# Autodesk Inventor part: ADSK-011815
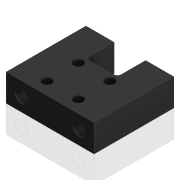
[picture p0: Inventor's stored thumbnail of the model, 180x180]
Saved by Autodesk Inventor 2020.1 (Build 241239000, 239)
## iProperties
Created: 1999-12
Part Number: ADSK-011815
Document SubType Name: Modeling
Designer: glanglot
Material: Générique
Density: 1 g/cm^3
Appearance: Rubber-Black
Mass: 572.86 g
Surface Area: 781.835 cm^2
Volume: 572.86 cm^3
Control State: 0
Master: False
Checked Out: False
Shininess: 0.0
Length Units: 11269
Angle Units: 11279
Time Units: 11290
Mass Units: 11283
Length Display Precision: 3
Angle Display Precision: 2
Compacted: True
Dimensions: 140x43x127 mm
Mass: 0,573 kg
Density: 0.0
Volumn: 0.0
Area: 0.0
PropertySet Name: Model Information
Author: glanglot
Revision Number: -
Title: ADSK-011815
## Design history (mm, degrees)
node "Solide1"
  node "Extrusion1" dims "d2" = 127, "d3" = 0
  node "Hole1" dims "d7" = 20, "d8" = 9.525, "d9" = 6.35, "d10" = 60 deg, "d11" = 19.05, "d12" = 118 deg, "d42" = 6
  node "Hole2" dims "d16" = 9, "d17" = 15, "d18" = 9, "d19" = 60 deg, "d20" = 19.05, "d21" = 118 deg, "d46" = 6
  node "Hole3" dims "d27" = 4.134, "d28" = 15.875, "d29" = 11.176, "d30" = 60 deg, "d31" = 14.2, "d32" = 118 deg, "d47" = 10
  node "Extrusion2" dims "d37" = 86.106, "d38" = 0
  node "Fillet1" dims "d39" = 6
sketch "Sketch1"
  geometry: L1 (100.269, -40.202)-(240.269, -40.202); L2 (240.269, -40.202)-(240.269, -83.202); L3 (240.269, -83.202)-(100.269, -83.202) reference; L4 (100.269, -83.202)-(100.269, -40.202) reference
  constraints: 8 end point, 2 horizontal, 2 parallel, 1 perpendicular, 1 vertical
  dimensions: "d0" = 43 distance of L3.end L1.start; "d1" = 140 distance of L2.end L3.end
sketch "Sketch2"
  geometry: L1 (100.269, -40.202)-(240.269, -40.202) reference; L2 (100.269, -83.202)-(100.269, -40.202) reference; L3 (124.269, -61.702)-(216.269, -61.702); 3 further points
  constraints: 3 midpoint, 2 end point, 2 horizontal alignment, 1 horizontal, 1 vertical alignment
  dimensions: "d5" = 92 distance of L3.end L3.start
sketch "Sketch3"
  geometry: L1 (0, -127)-(140, -127) reference; L2 (45, -57)-(95, -57); L3 (95, -57)-(95, -107); L4 (95, -107)-(45, -107); L5 (45, -107)-(45, -57); 4 further points
  constraints: 8 end point, 2 horizontal alignment, 2 midpoint, 2 parallel, 2 vertical alignment, 1 coincident, 1 horizontal, 1 perpendicular
  dimensions: "d43" = 20 distance between parallel lines of L1 L4; "d44" = 50 distance of L2.start L2.end; "d45" = 50 distance of L2.end L3.end
sketch "Sketch4"
  geometry: L1 (140, 127)-(0, 127) reference; L2 (6.5, 107)-(133.5, 107); L3 (133.5, 107)-(133.5, 18); L4 (133.5, 18)-(6.5, 18); L5 (6.5, 18)-(6.5, 107); L6 (0, 0)-(140, 0) reference; 4 further points
  constraints: 8 end point, 3 vertical alignment, 2 horizontal alignment, 2 midpoint, 2 parallel, 1 horizontal, 1 perpendicular
  dimensions: "d22" = 20 distance from line of L1 L2.start; "d23" = 89 distance of point (6.5, 18) L2.start; "d26" = 127 distance of point (133.5, 107) L2.start
sketch "Sketch5"
  geometry: L1 (0, -127)-(140, -127) reference; L2 (140, 0)-(0, 0) reference; L3 (0, 0)-(0, -127) reference; L4 (45, 0)-(45, -45); L5 (45, -45)-(95, -45); L6 (95, -45)-(95, 0); 2 further points
  constraints: 6 end point, 2 midpoint, 2 perpendicular, 2 point on line, 1 parallel, 1 vertical alignment
  dimensions: "d33" = 82 distance between parallel lines of L5 L1; "d36" = 50 distance between parallel lines of L6 L4
workplane "Work Plane1"
node "Corps solides"
node "Corps surfaciques"
other parameters: "d40" = -69.85
